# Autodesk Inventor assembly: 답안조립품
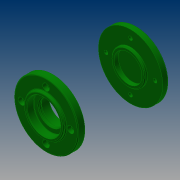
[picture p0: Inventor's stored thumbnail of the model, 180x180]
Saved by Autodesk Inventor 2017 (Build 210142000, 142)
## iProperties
Part Number: 답안조립품
Material: 일반
Document SubType Name: Assembly
Designer: 20
Author: 20
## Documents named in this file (4)
- C:\Users\20\Desktop\480310V1001\답안조립품.iam
- C:\Users\20\Desktop\480310V1001\본체.ipt
- C:\Users\20\Desktop\480310V1001\앞커버.ipt
- C:\Users\20\Desktop\480310V1001\뒤커버.ipt
